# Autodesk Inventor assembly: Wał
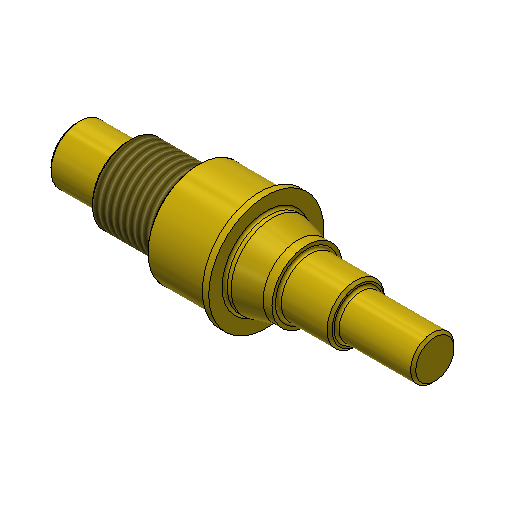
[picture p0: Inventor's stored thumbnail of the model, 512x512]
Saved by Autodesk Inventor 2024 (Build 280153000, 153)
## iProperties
Company: ATC
ClientObjectVersion: 1
Created: 2023-03
Part Number: Wał
Document SubType Name: Assembly
Designer: Andrzej Jaskulski
Checked By: A.J.
Engr Approved By: Andrzej Jaskulski
Mfg Approved By: Andrzej Jaskulski
Authority: A.J.
Title: A.J.: Kurs R2024-MEP
Author: Andrzej Jaskulski
Revision Number: 1/24
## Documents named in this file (2)
- C:\Users\AndJas\Documents\R2024-MEP\Obszar roboczy\PZ\PZ-Dane\Design Accelerator\Wał1.iam
- C:\Users\AndJas\Documents\R2024-MEP\Obszar roboczy\PZ\PZ-Dane\Design Accelerator\Wał1.ipt
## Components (1 placed, 1 different names)
1. Wał:1
